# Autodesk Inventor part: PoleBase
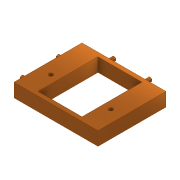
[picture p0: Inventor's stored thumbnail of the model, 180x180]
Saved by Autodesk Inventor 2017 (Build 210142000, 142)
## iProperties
Part Number: PoleBase
Material: ゴールド
Document SubType Name: Modeling
Designer: kyushu-hep
Density: 19.3 g/cm^3
Appearance: メタル 1600F 熱
Author: kyushu-hep
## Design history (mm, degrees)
sketch "スケッチ1"
  geometry: L1 (-9.744, 77.452)-(95.256, 77.452); L2 (95.256, 77.452)-(95.256, -7.548); L3 (95.256, -7.548)-(-9.744, -7.548); L4 (-9.744, -7.548)-(-9.744, 77.452); 1 further point
  constraints: 8 end point, 2 parallel, 1 horizontal, 1 perpendicular
  dimensions: "d0" = 105 distance of L2.end L3.end; "d1" = 85 distance of L3.end L1.start
extrude "押し出し1" new body sketch "スケッチ1" distance "d2" = 17; taper "d3" = 0 deg
sketch "スケッチ2"
  geometry: L1 (15.256, 72.452)-(70.256, 72.452); L2 (70.256, 72.452)-(70.256, -2.548); L3 (70.256, -2.548)-(15.256, -2.548); L4 (15.256, -2.548)-(15.256, 72.452); L5 (-9.744, -7.548)-(95.256, -7.548) reference; L6 (-9.744, 77.452)-(-9.744, -7.548) reference; 1 further point
  constraints: 8 end point, 2 parallel, 1 horizontal, 1 perpendicular
  dimensions: "d4" = 55 distance of L2.end L3.end; "d5" = 75 distance of L3.end L1.start; "d6" = 5 distance between parallel lines of L5 L3; "d7" = 25 distance between parallel lines of L6 L4
extrude "押し出し2" cut sketch "スケッチ2" distance "d8" = 20; taper "d9" = 0 deg
sketch "スケッチ3"
  geometry: L1 (0, 0)-(17, 0) reference; L2 (17, 5)-(17, 80) reference; L3 (0, 85)-(17, 85) reference; C1 r 5 at (7, 20); C2 r 5 at (7, 65); 1 further point
  constraints: 2 centre point
  dimensions: "d10" = 10 diameter of C1; "d11" = 20 distance from line of L1 C1.centre; "d12" = 10 distance from line of L2 C1.centre; "d13" = 10 diameter of C2; "d14" = 10 distance from line of C2.centre L2; "d15" = 20 distance from line of C2.centre L3
extrude "押し出し3" cut sketch "スケッチ3" distance "d16" = 2; taper "d17" = 0 deg
sketch "スケッチ4"
  geometry: L1 (10, 20)-(10, -65) reference; L2 (-7, 20)-(10, 20) reference; L3 (-7, -65)-(10, -65) reference; C1 r 2.5 at (0, 0); C2 r 2.5 at (0, -45); 1 further point
  constraints: 2 centre point
  dimensions: "d18" = 5 diameter of C1; "d19" = 10 distance from line of C1.centre L1; "d20" = 20 distance from line of C1.centre L2; "d21" = 5 diameter of C2; "d22" = 10 distance from line of L1 C2.centre; "d23" = 20 distance from line of C2.centre L3
extrude "押し出し4" join sketch "スケッチ4" distance "d24" = 12; taper "d25" = 0 deg
sketch "スケッチ6"
  geometry: L1 (0, 0)-(105, 0) reference; L2 (105, 0)-(105, -17) reference; L3 (0, 0)-(0, -17) reference; C1 r 5 at (75, -10); C2 r 5 at (30, -10); 1 further point
  constraints: 2 centre point
  dimensions: "d34" = 10 diameter of C1; "d35" = 10 distance from line of C1.centre L1; "d36" = 30 distance from line of C1.centre L2; "d37" = 10 diameter of C2; "d38" = 10 distance from line of C2.centre L1; "d39" = 30 distance from line of C2.centre L3
extrude "押し出し6" cut sketch "スケッチ6" distance "d40" = 2; taper "d41" = 0 deg
sketch "スケッチ7"
  geometry: L1 (30, 10)-(30, -7) reference; L2 (-75, 10)-(-75, -7) reference; L3 (-75, 10)-(30, 10) reference; C1 r 2.5 at (0, 0); C2 r 2.5 at (-45, 0); 1 further point
  constraints: 2 centre point
  dimensions: "d42" = 5 diameter of C1; "d43" = 5 diameter of C2; "d44" = 30 distance from line of C1.centre L1; "d45" = 30 distance from line of L2 C2.centre; "d46" = 10 distance from line of L3 C2.centre; "d47" = 10 distance from line of L3 C1.centre
extrude "押し出し7" join sketch "スケッチ7" distance "d48" = 12; taper "d49" = 0 deg
sketch "スケッチ8"
  geometry: L1 (-9.744, 77.452)-(-9.744, -7.548) reference; L2 (-9.744, -7.548)-(95.256, -7.548) reference; L3 (95.256, -7.548)-(95.256, 77.452) reference; C1 r 2.5 at (5.256, 23.452); C2 r 2.5 at (80.256, 23.452); 1 further point
  constraints: 2 centre point
  dimensions: "d50" = 5 diameter of C1; "d51" = 15 distance from line of C1.centre L1; "d52" = 31 distance from line of C1.centre L2; "d53" = 5 diameter of C2; "d54" = 31 distance from line of L2 C2.centre; "d55" = 15 distance from line of L3 C2.centre
extrude "押し出し8" cut sketch "スケッチ8" stored distance "d56" = 50; taper "d57" = 0 deg
node "ソリッド1"
